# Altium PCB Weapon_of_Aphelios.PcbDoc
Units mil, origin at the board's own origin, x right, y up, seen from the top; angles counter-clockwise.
Board outline 1771.65 x 1968.5 mil, 2 copper layers (Top Layer, Bottom Layer); 49 components, 29 nets, 186 pads, 53 vias.
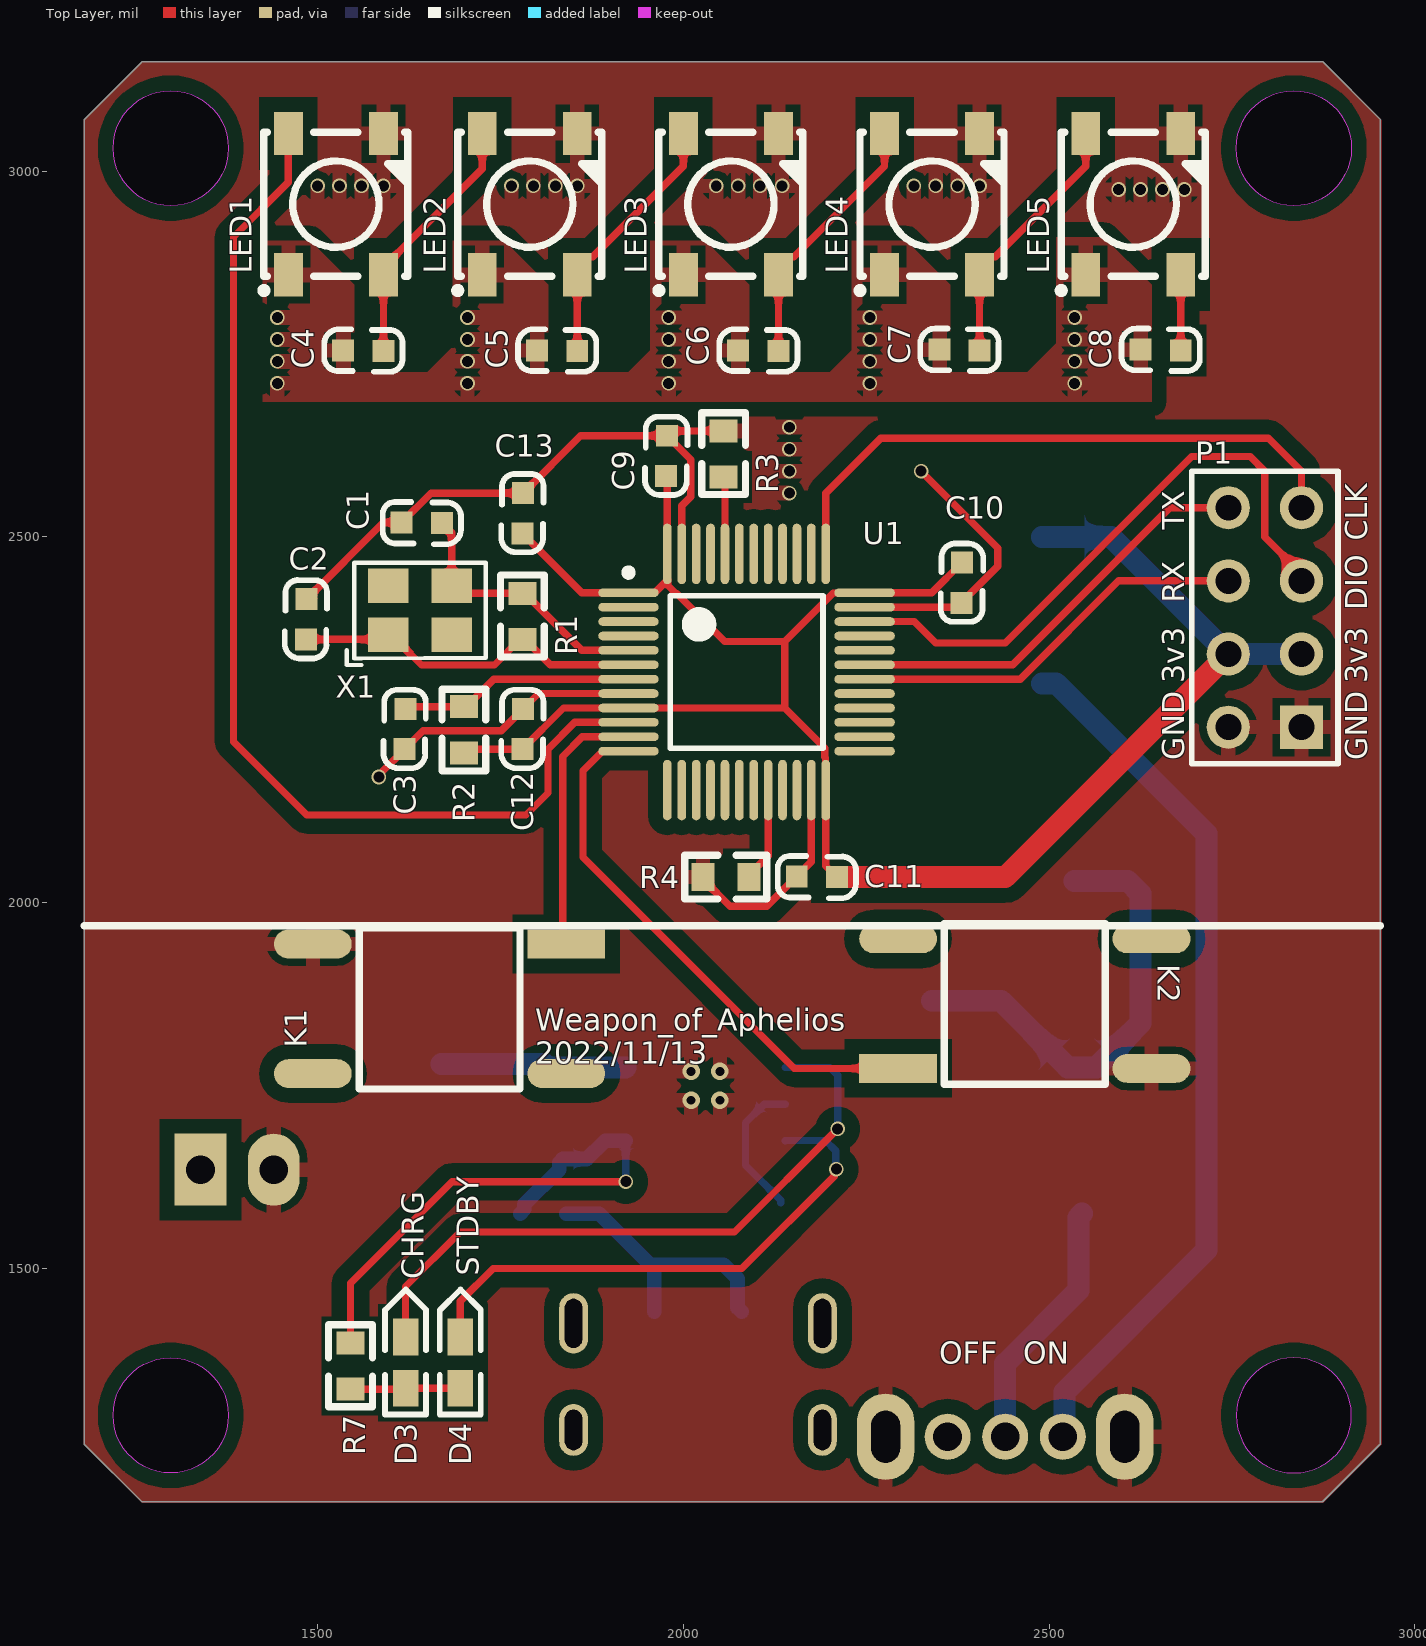
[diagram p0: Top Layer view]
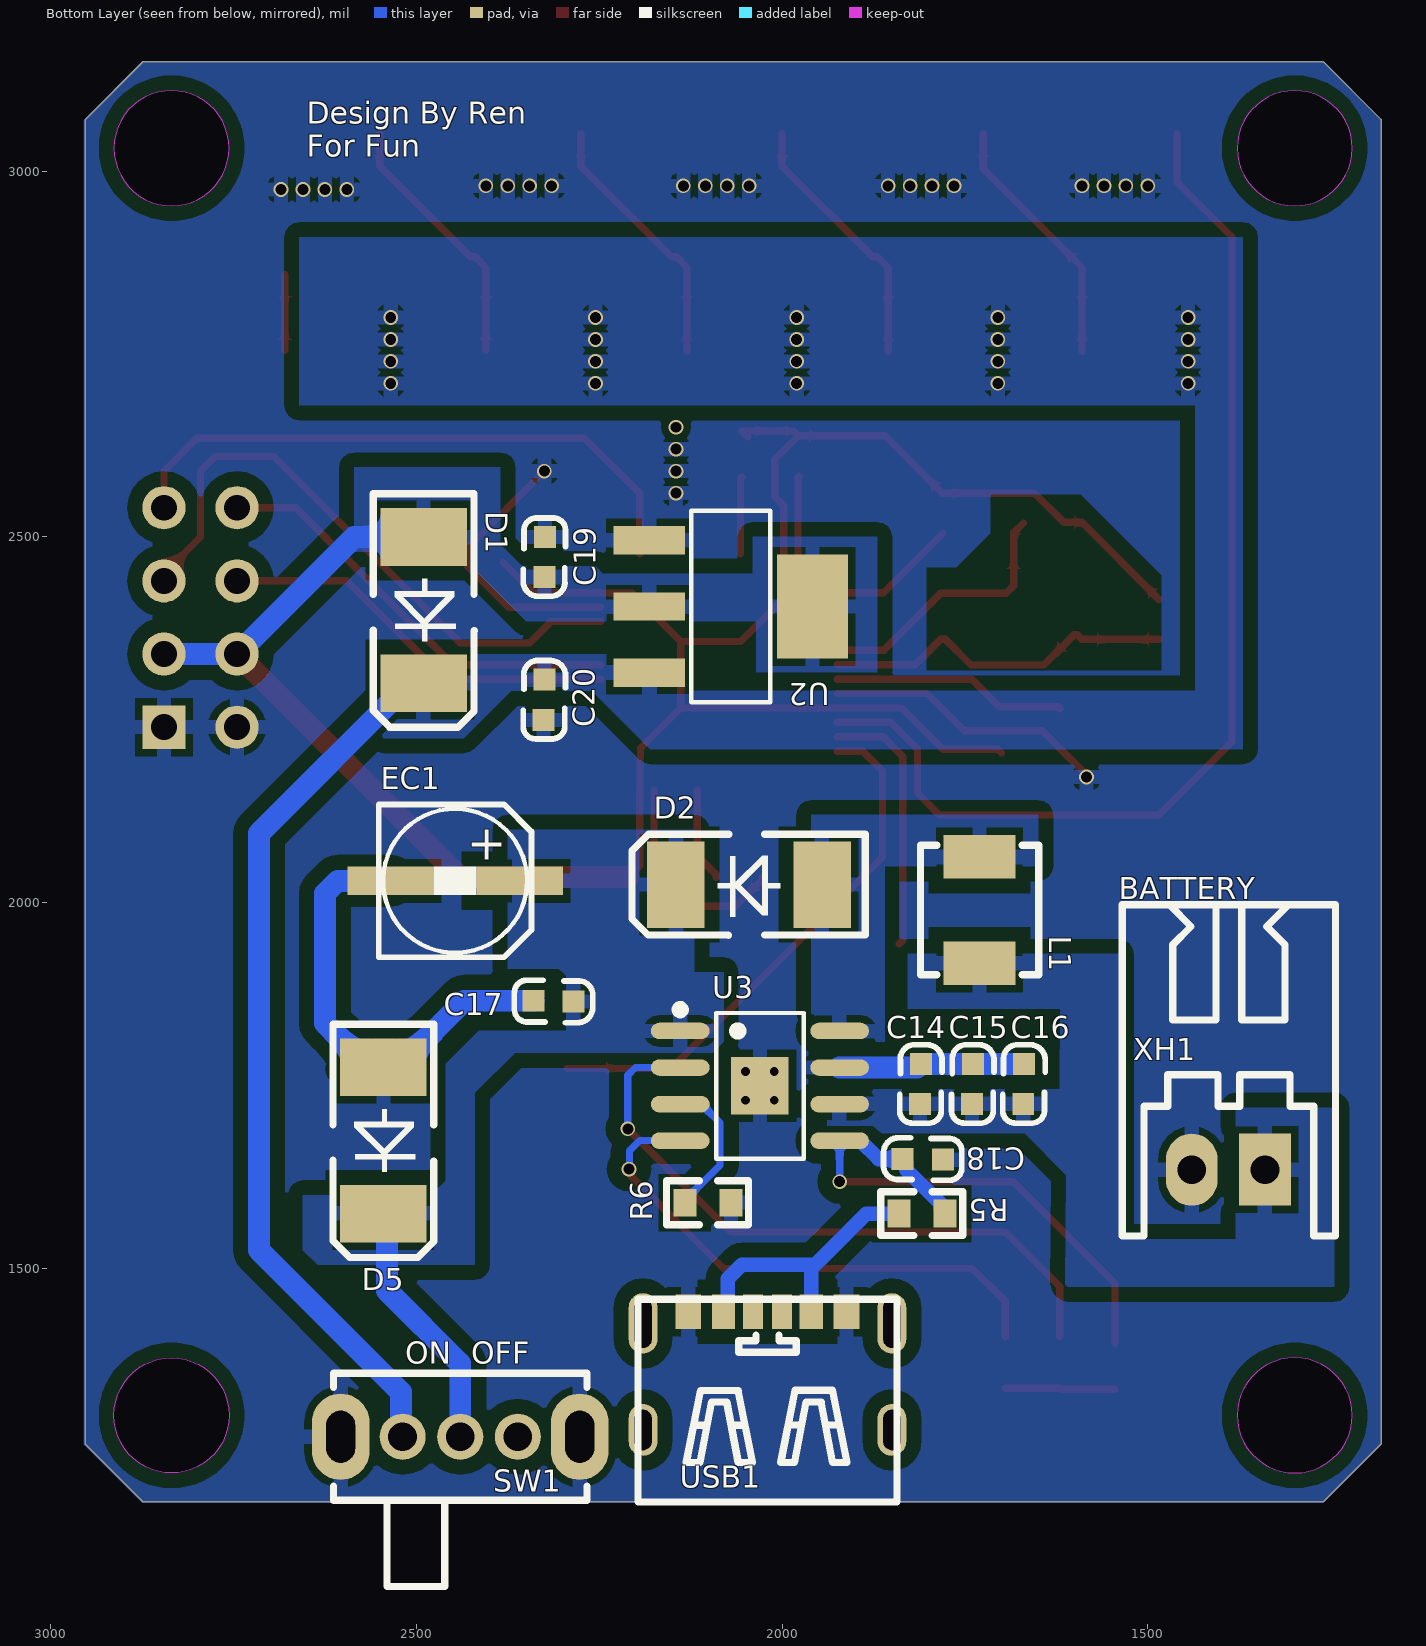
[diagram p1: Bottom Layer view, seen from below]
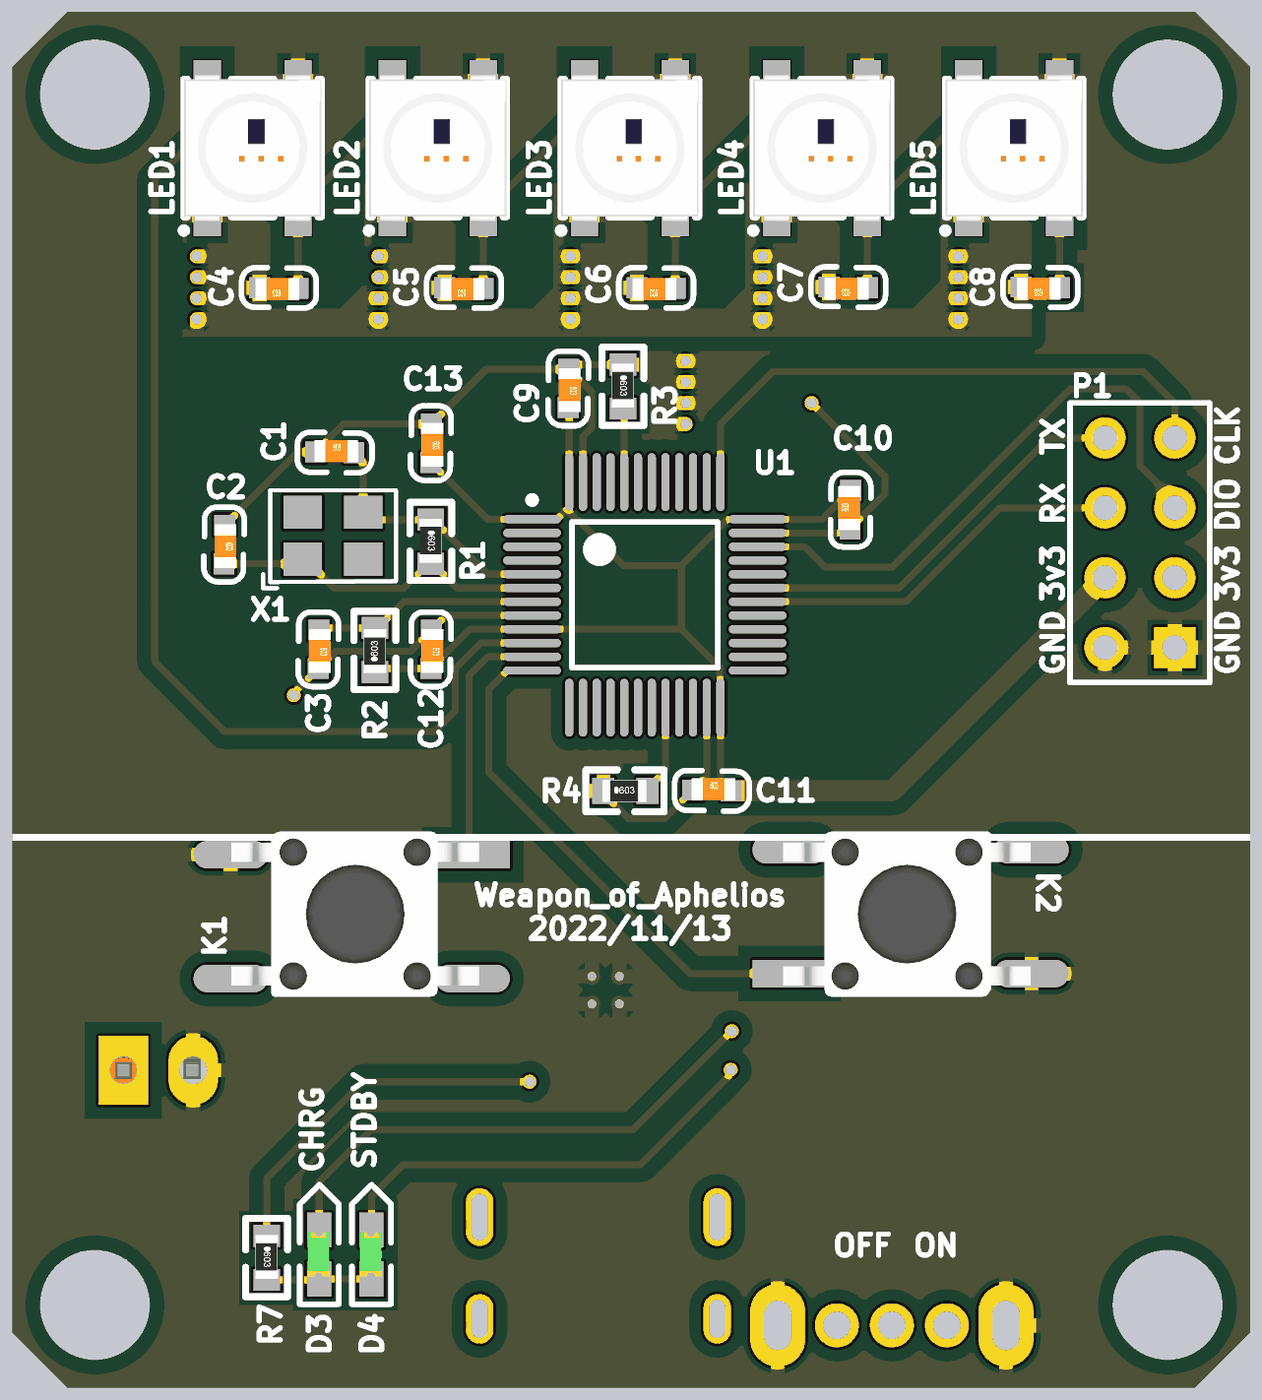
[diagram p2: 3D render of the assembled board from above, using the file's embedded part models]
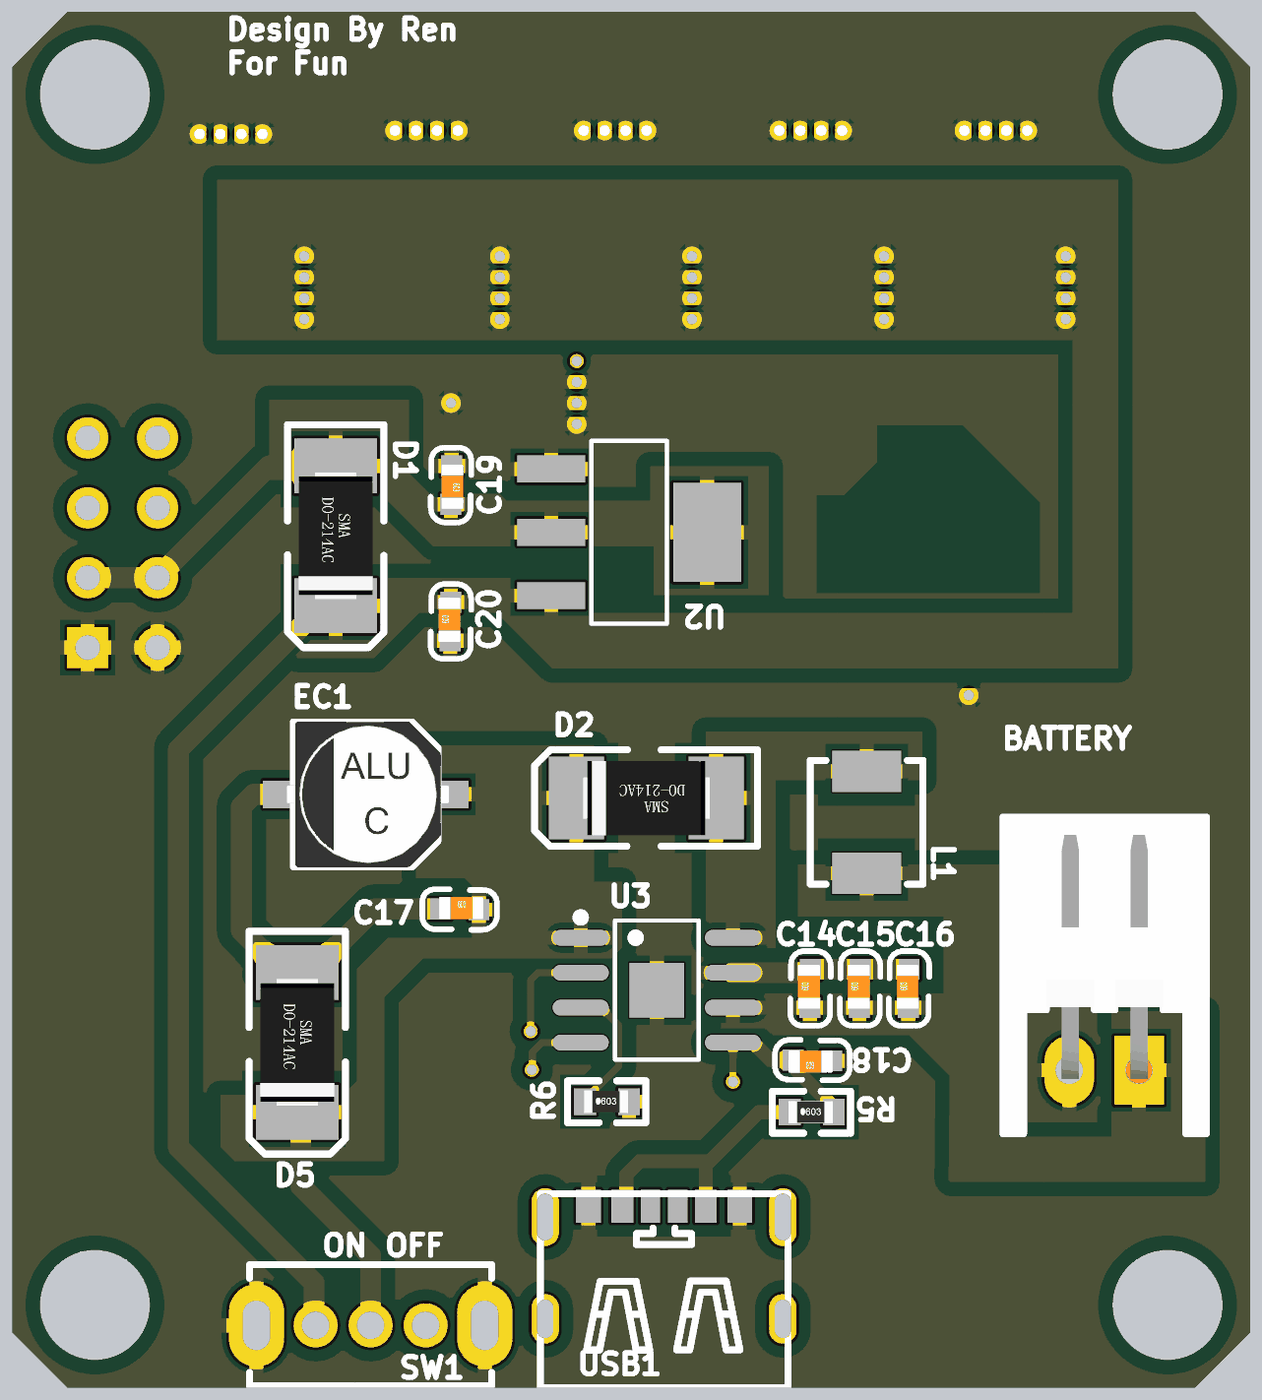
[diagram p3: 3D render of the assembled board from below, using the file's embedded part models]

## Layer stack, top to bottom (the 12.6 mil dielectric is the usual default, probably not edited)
Top Solder: solder mask 0.4, Solder Resist, Dk 3.5
Top Layer: signal copper 1.4
Dielectric 1: dielectric 12.6, FR-4, Dk 4.8
Bottom Layer: signal copper 1.4
Bottom Solder: solder mask 0.4, Solder Resist, Dk 3.5

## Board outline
1259.84,1181.1 1181.1,1259.84 1181.1,3070.87 1259.84,3149.61 2874.02,3149.61 2952.76,3070.87 2952.76,1259.84 2874.02,1181.1
cut-out: 1299.21,1220.47 cw(c1299.21,1299.21) 1220.47,1299.21 cw(c1299.21,1299.21) 1299.21,1377.95 cw(c1299.21,1299.21) 1377.95,1299.21 cw(c1299.21,1299.21)
cut-out: 2755.91,1299.21 ccw(c2834.65,1299.21) 2834.65,1220.47 ccw(c2834.65,1299.21) 2913.39,1299.21 ccw(c2834.65,1299.21) 2834.65,1377.95 ccw(c2834.65,1299.21)
cut-out: 2834.65,2952.76 cw(c2834.65,3031.5) 2755.91,3031.5 cw(c2834.65,3031.5) 2834.65,3110.24 cw(c2834.65,3031.5) 2913.39,3031.5 cw(c2834.65,3031.5)
cut-out: 1299.21,2952.76 cw(c1299.21,3031.5) 1220.47,3031.5 cw(c1299.21,3031.5) 1299.21,3110.24 cw(c1299.21,3031.5) 1377.95,3031.5 cw(c1299.21,3031.5)

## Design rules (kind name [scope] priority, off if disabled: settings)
Clearance MCU [InComponent('U1') vs InComponent('U1')] p1: gap=8 ignorepadtopadclearanceinfootprint=TRUE except(0: Arc-Hole Track-Hole SMDPad-Hole THPad-Hole Via-Hole Fill-Hole Poly-Hole Region-Hole Text-Hole)
Clearance [All] p2: gap=8 ignorepadtopadclearanceinfootprint=TRUE except(0: Arc-Hole Track-Hole SMDPad-Hole THPad-Hole Via-Hole Fill-Hole Poly-Hole Region-Hole Text-Hole)
PlaneConnect [All] p1: planeconnectstyle=Relief reliefexpansion=20 reliefentries=4 reliefconductorwidth=20 reliefairgap=10
PolygonConnect [All] p1: connectstyle=Relief reliefconductorwidth=20 reliefentries=4 polygonreliefangle="90 Angle" airgapwidth=10
RoutingVias [All] p1: holewidth=15 width=20 viastyle="Through Hole" minholewidth=15 minwidth=20 maxholewidth=30 maxwidth=40
SolderMaskExpansion [All] p1: expansion=4 istentingtop=FALSE
Width [All] p1: maxlimit=30 minlimit=10 preferedwidth=20
29 further rules are at their usual default settings.

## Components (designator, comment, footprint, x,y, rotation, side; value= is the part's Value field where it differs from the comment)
C1 "22pF" 0603C 1614.79,2520.35 r0 top
C2 "22pF" 0603C 1485.35,2415.21 r270 top
C3 "100nF" 0603C 1620.35,2265.21 r270 top
C4 "100nF" 0603C 1590.21,2753.65 r180 top
C5 "100nF" 0603C 1855.21,2753.65 r180 top
C6 "100nF" 0603C 2130.21,2753.65 r180 top
C7 "100nF" 0603C 2405.21,2754.65 r180 top
C8 "100nF" 0603C 2680.21,2754.65 r180 top
C9 "100nF" 0603C 1977.93,2638.64 r270 top
C10 "100nF" 0603C 2379.65,2409.79 r90 top
C11 "100nF" 0603C 2154.79,2036.35 r0 top
C12 "100nF" 0603C 1781.35,2265.21 r270 top
C13 "100nF" 0603C 1781.35,2560.21 r270 top
C14 "0.1uF" 0603C 1811.65,1724.49 r90 bottom
C15 "22uF" 0603C 1740.65,1724.49 r90 bottom
C16 "22uF" 0603C 1670.65,1724.49 r90 bottom
C17 "100nF" 0603C 2340.21,1866.35 r180 bottom
C18 "10uF" 0603C 1780.09,1648.35 r0 bottom
C19 "10uF" 0603C 2323.65,2500.21 r270 bottom
C20 "10uF" 0603C 2326.35,2249.79 r90 bottom
D1 "SS34-MS" SMA/DO-214AC 2490,2495 r270 bottom
D2 "SS34-MS" SMA/DO-214AC 1950.3,2024.7 r0 bottom
D3 "CHRG" LED-0603B 1620.56,1336.3 r90 top
D4 "STDBY" LED-0603B 1695.3,1336.3 r90 top
D5 "SMAJ6.0A" SMA/DO-214AC 2545,1770 r270 bottom
EC1 "47uF" SMD-EC5.0X5.3X5.4 2358.75,2030 r0 bottom
K1 "KEY" SMD-6X6X6 1836.77,1945.43 r270 top
K2 "KEY" SMD-6X6X6 2296.77,1771.65 r90 top
L1 "10uH" IND-SMD_L4.5-W4.1_TMPA0402SP 1730,1990 r270 bottom
LED1 "WS2812B-B" LED-SMD_4P-L5.0-W5.0-TL_WS2812B-B 1525,2955 r90 top
LED2 "WS2812B-B" LED-SMD_4P-L5.0-W5.0-TL_WS2812B-B 1790,2955 r90 top
LED3 "WS2812B-B" LED-SMD_4P-L5.0-W5.0-TL_WS2812B-B 2065,2955 r90 top
LED4 "WS2812B-B" LED-SMD_4P-L5.0-W5.0-TL_WS2812B-B 2340,2955 r90 top
LED5 "WS2812B-B" LED-SMD_4P-L5.0-W5.0-TL_WS2812B-B 2615,2955 r90 top
P1 "Header 4X2" HDR2X4 2845,2240 r90 top
R1 "1M" 0603R 1780,2422.99 r270 top
R2 "10K" 0603R 1700,2205 r90 top
R3 "10K" 0603R 2055,2645 r270 top
R4 "10K" 0603R 2027.01,2035 r0 top
R5 "0.3" 0603R 1840,1575 r180 bottom
R6 "3k" 0603R 2132.99,1590 r180 bottom
R7 "1K" 0603R 1545,1397.99 r270 top
SW1 "SK12D07VG3_C431547" SW-TH_SK12D07VG3 2440,1270 r180 bottom
U1 "STM32F103C" LQFP-48_M 2086.42,2315.47 r0 top
U2 "AMS1117-3.3_C369933" SOT-223-4_L6.5-W3.5-P2.30-LS7.0-BR 2070,2405 r0 bottom
U3 "TP5400" SOIC-8_L5.0-W4.0-P1.27-LS6.0-BL-EP2.0 2030.3,1749.7 r270 bottom
USB1 "TYPE-C-31-M-16" TYPE-C-31-M-16 2020,1360 r180 bottom
X1 "8MHz" OSC-SMD_4P-L3.2-W2.5-BL 1640,2400 r0 top
XH1 "XH2" XH2/2.54mm/90 1340,1635 r0 bottom

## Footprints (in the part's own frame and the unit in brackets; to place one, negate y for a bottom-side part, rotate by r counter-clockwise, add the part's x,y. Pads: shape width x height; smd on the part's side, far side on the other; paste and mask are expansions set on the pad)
0603C [mil]
  rect 30x30 smd: 1(0.21,-0.35) 2(55.21,-1.35)
  silkscreen extent -26,-30 81,28, body extent -1,-15 62,17, height 12
0603R [mm]
  rect 0.8x0.965 smd: 1(0,0) 2(1.6,0)
  silkscreen extent -0.64,-0.76 2.21,0.76, body extent -0.04,-0.41 1.56,0.41, height 0.45
HDR2X4 [mm] "Connector; Header; 4x2 Position"
  rect 1.5x1.5 hole 0.9: 1(0,0)
  round 1.5 hole 0.9: 2(0,2.54) 3(2.54,0) 4(2.54,2.54) 5(5.08,0) 6(5.08,2.54) 7(7.62,0) 8(7.62,2.54)
  silkscreen extent -1.27,-1.27 8.89,3.81
IND-SMD_L4.5-W4.1_TMPA0402SP [mm]
  rect 1.5x2.5 smd mask+0.051: 1(-1.85,0) 2(1.85,0)
  silkscreen extent -2.25,-2.05 2.25,2.05
LED-0603B [mil]
  rect 50x35 smd: A(0,0.26) K(70,0.26)
  silkscreen extent -36,-28 135,28, body extent 4,-15 66,17, height 24
LED-SMD_4P-L5.0-W5.0-TL_WS2812B-B [mm]
  rect 1.5x1 smd mask+0.051: 1(-2.45,1.65) 2(-2.45,-1.65) 3(2.45,-1.65) 4(2.45,1.65)
  silkscreen extent -3.1,-2.5 2.5,2.6, body extent -2.7,-2.5 2.7,2.5, height 1.57
LQFP-48_M [mm] "Thin QFP, 48-Leads, Body 7x7mm, Pitch 0.5mm, IPC Low Density"
  oval 2.1x0.3 smd: 1(-4.1,2.75) 2(-4.1,2.25) 3(-4.1,1.75) 4(-4.1,1.25) 5(-4.1,0.75) 6(-4.1,0.25) 7(-4.1,-0.25) 8(-4.1,-0.75) 9(-4.1,-1.25) 10(-4.1,-1.75) 11(-4.1,-2.25) 12(-4.1,-2.75) 25(4.1,-2.75) 26(4.1,-2.25) 27(4.1,-1.75) 28(4.1,-1.25) 29(4.1,-0.75) 30(4.1,-0.25) 31(4.1,0.25) 32(4.1,0.75) 33(4.1,1.25) 34(4.1,1.75) 35(4.1,2.25) 36(4.1,2.75)
  oval 0.3x2.1 smd: 13(-2.75,-4.1) 14(-2.25,-4.1) 15(-1.75,-4.1) 16(-1.25,-4.1) 17(-0.75,-4.1) 18(-0.25,-4.1) 19(0.25,-4.1) 20(0.75,-4.1) 21(1.25,-4.1) 22(1.75,-4.1) 23(2.25,-4.1) 24(2.75,-4.1) 37(2.75,4.1) 38(2.25,4.1) 39(1.75,4.1) 40(1.25,4.1) 41(0.75,4.1) 42(0.25,4.1) 43(-0.25,4.1) 44(-0.75,4.1) 45(-1.25,4.1) 46(-1.75,4.1) 47(-2.25,4.1) 48(-2.75,4.1)
  silkscreen extent -4.22,-2.65 2.65,3.57, body extent -3.5,-3.5 3.5,3.5, height 1.6
OSC-SMD_4P-L3.2-W2.5-BL [mm]
  rect 1.4x1.2 smd: 1(-1.1,-0.851) 2(1.1,-0.851) 3(1.1,0.851) 4(-1.1,0.851)
  silkscreen extent -2.54,-1.91 2.29,1.65
SMA/DO-214AC [mm] "塑封二极管"
  rect 2x3 smd: A(-0.127,0) K(4.953,0)
  silkscreen extent -1.63,-1.75 6.48,1.75, body extent 0.11,-1.35 4.71,1.35, height 2.4
SMD-6X6X6 [mm]
  rect 1x2.7 smd: 1(0.047,0.082)
  oval 1x2.7 smd: 2(4.547,0.082) 3(0.047,-8.718) 4(4.547,-8.718)
  silkscreen extent -0.51,-7.11 5.08,-1.52, body extent -0.79,-8.69 5.21,0.31, height 5.95
SMD-EC5.0X5.3X5.4 [mm]
  rect 3x1 smd: 1(0,0) 2(4.477,0)
  silkscreen extent -0.41,-2.65 4.89,2.66, body extent -0.79,-2.65 5.11,2.65, height 5.41
SOIC-8_L5.0-W4.0-P1.27-LS6.0-BL-EP2.0 [mil]
  oval 22.6x80.2 smd mask+2: 1(-75,-109) 2(-25,-109) 3(25,-109) 4(75,-109) 5(75,109) 6(25,109) 7(-25,109) 8(-75,109)
  rect 78.7x78.7 smd mask+2: 9(0,0)
  silkscreen extent -110,-115 100,60
SOT-223-4_L6.5-W3.5-P2.30-LS7.0-BR [mm]
  rect 2.47x0.98 smd: 1(2.835,-2.3) 2(2.835,0) 3(2.835,2.3)
  rect 2.47x3.6 smd: 4(-2.835,0)
  silkscreen extent -1.37,-3.33 1.37,3.33
SW-TH_SK12D07VG3 [mm]
  round 1.6 hole 1: 1(-2,0) 2(0,0) 3(2,0)
  oval 2x3 hole 1 slot 1.8 at 90 deg: 4(4.15,0) 5(-4.15,0)
  silkscreen extent -4.4,-5.2 4.4,2.2
TYPE-C-31-M-16 [mm]
  oval 1x2.1 hole 0.6 slot 1.7 at 90 deg: 1(-4.32,1.65) 2(4.32,1.65)
  oval 1x1.8 hole 0.6 slot 1.4 at 90 deg: 3(-4.32,-2.05) 4(4.32,-2.05)
  rect 0.7x1.2 smd: A5(-0.5,2.05) B5(0.5,2.05)
  rect 0.8x1.2 smd: A9(1.52,2.05) B9(-1.52,2.05)
  rect 0.9x1.2 smd: A12(2.75,2.05) B12(-2.75,2.05)
  silkscreen extent -4.5,-4.55 4.5,2.49
XH2/2.54mm/90 [mm]
  rect 1.8x2.5 hole 1: 1(0,0)
  oval 1.8x2.5 hole 1: 2(2.54,0)
  silkscreen extent -2.45,-9.2 4.95,2.3, body extent -2.45,-9.2 4.95,2.3, height 6.1

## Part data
C1 C2: library part CAP
C3 C4 C5 C6 C7 C8 C9 C10 C11 C12 C13 C14 C15 C16 C17 C18 C19 C20: library part CAP, "无极性电容"
D1 D2: library part "DIODE SCHOTTKY", "肖特基二极管"
D3 D4: library part LED
D5: library part "DIODE ZENER", "瞬态二极管 SMAJ6.0A DO-214AC 6.0V"
EC1: library part SMD_ECAP, "贴片电解电容"
L1: library part TMPC0402HP-100MG-Z02, DC Resistance (DCR)=215mΩ, JLCPCB Part Class="Extended Part", LCSC Part Name="10uH ±20% 1.4A 215mΩ", Manufacturer=台庆, Rated Current=1.4A, Tolerance=±20%
LED1 LED2 LED3 LED4 LED5: Emitted Color=RGB三色, JLCPCB Part Class="Extended Part", LCSC Part Name="RGB三色 （注意防潮，请查阅规格书中对应具体内容）", Manufacturer=worldsemi
P1: "Header, 4-Pin, Dual row"
R1 R2 R3 R4 R5 R6 R7: library part RES
SW1: BOM_JLCPCB Part Class="Extended Part", BOM_Manufacturer="SHOU HAN", BOM_Manufacturer Part=SK12D07VG3
U1: "STM32单片机48引脚"
U2: BOM_Manufacturer=KEXIN, BOM_Manufacturer Part=AMS1117-3.3
U3: Battery Pack Voltage=-, JLCPCB Part Class="Extended Part", Manufacturer=TOPPOWER(南京拓微)
X1: library part "8MHz 10pF ±10ppm", BOM_Manufacturer="Zhejiang Abel Elec", BOM_Manufacturer Part=TAXM8M4RDBCCT2T

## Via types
v1: diameter 20, hole 15, Top Layer to Bottom Layer, 49 vias
v2: diameter 24, hole 12, Top Layer to Bottom Layer, 4 vias

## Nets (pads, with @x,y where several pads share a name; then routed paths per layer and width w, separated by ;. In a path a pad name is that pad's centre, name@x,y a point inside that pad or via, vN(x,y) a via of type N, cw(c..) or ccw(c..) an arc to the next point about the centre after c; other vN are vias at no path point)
3v3: C9.2 C10.2 C11.2 C12.2 C13.2 C19.2 D1.A P1.3 P1.4 R2.1 U1.1 U1.9 U1.24 U1.36 U1.48 U2.2 U2.4 | length 2766.3
  Top Layer w10: R2.1 1705,2210 C12.2 1836.26,2266.26 U1.9 2138.74,2266.26 ; C13.2 1861.26,2423.74 U1.1 1960.78,2423.74 1978.5,2441.46 1978.5,2434.06 ; C9.2 1978.15,2581.85 U1.48 U1.48@1978.15,2441.46 ; 1978.93,2433.63 1990,2422.55 1991.23,2422.55 2056.65,2357.13 2138.74,2357.13 ; C11.2 2194.68,2050.32 U1.24 2194.34,2154.4 2194.34,2198.53 2193.5,2199.37 2193.5,2211.5 2138.74,2266.26 ; C10.2 2339.74,2423.74 U1.36 2247.49,2423.39 2205,2423.39 2138.74,2357.13 ; 2138.74,2266.26 2138.74,2357.13
  Top Layer w30: C11.2 2440,2035 P1.4
  Bottom Layer w30: D1.A 2585,2500 P1.4 P1.3
5V: C4.2 C5.2 C6.2 C7.2 C8.2 C20.2 D1.K LED1.1 LED2.1 LED3.1 LED4.1 LED5.1 SW1.1 U2.3 | length 1216
  Bottom Layer w30: D1.K 2509.68,2300 2715,2094.68 2715,1525 2520.96,1330.96 2520.96,1272.22 SW1.1
  other v1: 1445,2710 1705,2710 1980,2710 2255,2710 2535,2710 1445,2740 1705,2740 1980,2740 2255,2740 2535,2740 1445,2770 1705,2770 1980,2770 2255,2770 2535,2770 1445,2800 1705,2800 1980,2800 2255,2800 2535,2800
BAT: C14.1 C15.1 C16.1 L1.2 U3.6 XH1.1
DIN: LED1.4 U1.10 | length 1531.5
  Top Layer w10: LED1.4 1460.04,2985.04 1385,2910 1385,2220 1485,2120 1785,2120 1815,2150 1815,2210 1851.57,2246.57 U1.10
GND: C1.1 C2.1 C3.2 C9.1 C10.1 C11.1 C12.1 C13.1 C14.2 C15.2 C16.2 C17.1 C18.1 C19.1 C20.1 D5.A EC1.2 K1.3 K2.3 LED1.3 LED2.3 LED3.3 LED4.3 LED5.3 P1.1 P1.2 R3.1 R4.1 R6.2 SW1.4 SW1.5 U1.8 U1.23 U1.35 U1.47 U2.1 U3.7 U3.9 USB1.A12 USB1.B12 XH1.2 | length 2791.5
  Top Layer w10: C2.1 1590,2520 C1.1 1655,2560 C13.1 1859.43,2638.43 C9.1 ; v1(1583.83,2171.83) 1585.74,2173.74 1585.74,2176.74 C3.2 1644,2235 1751,2235 C12.1 1801.94,2285.94 U1.8 ; U1.47 1997.83,2542.83 2010,2555 2010,2606 C9.1 ; R4.1 2027.01,2031.75 2063.76,1995 2114,1995 C11.1 2175,2056 U1.23 ; R3.1@2047.01,2637.01 R3.1 1984.15,2645 C9.1 ; U1.35 2374.06,2404.06 C10.1 2430,2460 2430,2485 v1(2325,2590)
  Bottom Layer w30: C16.2 C15.2 C14.2 1815.3,1774.7 U3.7 ; C17.1 2434.32,1866 2525.32,1775 D5.A 2564.68,1775 2625,1835.32 2625,2012.43 2607.43,2030 EC1.2
  other v1: 2145,2560 2145,2590 2145,2620 2145,2650 2595,2975 2625,2975 2655,2975 2685,2975 1500,2980 1530,2980 1560,2980 1590,2980 1765,2980 1795,2980 1825,2980 1855,2980 2045,2980 2075,2980 2105,2980 2135,2980 2315,2980 2345,2980 2375,2980 2405,2980
  other v2: 2010.6,1730 2050,1730 2010.6,1769.4 2050,1769.4
KEY1: K1.1 U1.11 | length 359.6
  Top Layer w10: K1.1 1835,1948.6 1835,2200 1861.89,2226.89 U1.11
KEY2: K2.1 U1.12 | length 741.8
  Top Layer w10: U1.12 1889.57,2207.2 1862.82,2180.46 1862.82,2062.18 2151.51,1773.49 K2.1
NetC1_2: C1.2 R1.1 U1.5 X1.3 | length 369.4
  Top Layer w10: C1.2 1683.3,2505.7 X1.3 1693.82,2422.99 R1.1 1783.25,2422.99 1861.24,2345 U1.5
NetC2_2: C2.2 R1.2 U1.6 X1.1 | length 489.7
  Top Layer w10: C2.2 1590.19,2360 X1.1 1600.63,2366.5 1642.13,2325 1741.75,2325 1776.75,2360 R1.2 1783.25,2360 1817.93,2325.32 U1.6
NetC3_1: C3.1 R2.2 U1.7 | length 321.8
  Top Layer w10: C3.1 1622.99,2267.99 R2.2 1703.25,2267.99 1740.89,2305.63 U1.7
NetC4_1: C4.1 LED1.2 LED2.4 | length 353.4
  Top Layer w10: C4.1 LED1.2 LED1.2 1589.96,2868.39 1725.04,3003.47 LED2.4
NetC5_1: C5.1 LED2.2 LED3.4 | length 361.4
  Top Layer w10: C5.1 LED2.2 LED2.2 1854.96,2868.39 1869.64,2883.07 1876.18,2883.07 2000.04,3006.93 LED3.4
NetC6_1: C6.1 LED3.2 LED4.4 | length 361.4
  Top Layer w10: C6.1 LED3.2 LED3.2 2129.96,2868.39 2144.64,2883.07 2151.18,2883.07 2275.04,3006.93 LED4.4
NetC7_1: C7.1 LED4.2 LED5.4 | length 360.4
  Top Layer w10: C7.1 C7.1 LED4.2 2404.96,2868.39 2419.64,2883.07 2426.18,2883.07 2550.04,3006.93 LED5.4
NetC8_1: C8.1 LED5.2 | length 103.6
  Top Layer w10: LED5.2 C8.1 C8.1
NetC18_2: C18.2 R5.2 R7.1 U3.5 | length 767
  Top Layer w10: R7.1 1545,1480 1683.7,1618.7 v1(1921.3,1618.7)
  Bottom Layer w10: v1(1921.3,1618.7) U3.5
  Bottom Layer w20: R5.2 1782.76,1580.75 1782.76,1587.76 1830.3,1635.3 1830.3,1644.7 C18.2 1868.2,1649.7 1892,1673.5 1893.2,1674.7 U3.5
NetD2_A: D2.A L1.1 U3.8
NetD3_A: D3.A D4.A R7.2 | length 150.6
  Top Layer w10: R7.2 1619,1335 D3.A D4.A
NetD3_K: D3.K U3.2 | length 898.1
  Top Layer w10: D3.K 1620.3,1475.3 1695,1550 2070,1550 v1(2210.89,1690.89)
  Bottom Layer w10: U3.2 2200.3,1774.7 2210.89,1764.11 v1(2210.89,1690.89)
NetD4_K: D4.K U3.4 | length 742
  Top Layer w10: D4.K 1695.04,1455.04 1740,1500 2080,1500 2206.29,1626.29 2206.29,1630.08 2209.25,1633.04 v1(2209.25,1635.75)
  Bottom Layer w10: U3.4 2139.45,1674.85 2194.4,1674.85 2208.5,1660.75 2208.5,1636.5 v1(2209.25,1635.75)
NetR3_2: R3.2 U1.44 | length 105.9
  Top Layer w10: R3.2 2056.89,2580.12 U1.44
NetR4_2: R4.2 U1.20 | length 129.8
  Top Layer w10: R4.2 2090,2038.25 2115.94,2064.19 U1.20
NetR6_1: R6.1 U3.3 | length 193.9
  Bottom Layer w10: R6.1 2132.99,1593.25 2085,1641.24 2085,1699.2 2110.5,1724.7 U3.3
SWCLK: P1.7 U1.37 | length 832.9
  Top Layer w10: U1.37 2194.68,2559.68 2270,2635 2800,2635 2845,2590 P1.7
SWDIO: P1.5 U1.34 | length 844
  Top Layer w10: U1.34 2315.63,2384.37 2345,2355 2440,2355 2695,2610 2775,2610 2795,2590 2795,2500 2845,2450 P1.5
USART1_RX: P1.8 U1.31 | length 586.1
  Top Layer w10: U1.31 2450.32,2325.32 2665,2540 P1.8
USART1_TX: P1.6 U1.30 | length 552.8
  Top Layer w10: U1.30 2460.63,2305.63 2595,2440 P1.6
VCC: R5.1 USB1.A9 USB1.B9 | length 385
  Bottom Layer w20: R5.1 1885,1575 1955,1505 ; USB1.A9 1960.15,1499.85 1955,1505 ; USB1.B9 2074.1,1446.46 2074.1,1485.9 2055,1505 1955,1505
VOUT: C17.2 D2.K D5.K EC1.1 SW1.2 U3.1 | length 340
  Bottom Layer w30: SW1.2@2440,1278.54 2440,1370 2540,1470 2540,1570 D5.K
pads on no net: K1.2 K1.4 K2.2 K2.4 SW1.3 U1.2 U1.3 U1.4 U1.13 U1.14 U1.15 U1.16 U1.17 U1.18 U1.19 U1.21 U1.22 U1.25 U1.26 U1.27 U1.28 U1.29 U1.32 U1.33 U1.38 U1.39 U1.40 U1.41 U1.42 U1.43 U1.45 U1.46 USB1.1 USB1.2 USB1.3 USB1.4 USB1.A5 USB1.B5 X1.2 X1.4

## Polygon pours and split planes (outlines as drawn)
GND on Top Layer "GND_L01_P011" (solid, remove dead copper, pour order 11): 1260,3150 2875,3150 2955,3070 2955,1260 2875,1180 1260,1180 1180,1260 1180,3070
5V on Top Layer "5V_L01_P001" (solid, remove dead copper, pour order 1): 1425,2685 2640,2685 2640,2845 2575,2910 2510,2910 2510,2765 2470,2725 2365,2725 2365,2845 2305,2905 2230,2905 2230,2755 2200,2725 2090,2725 2090,2845 2030,2905 1955,2905 1955,2755 1925,2725 1815,2725 1815,2845 1755,2905 1685,2905 1685,2760 1650,2725 1550,2725 1550,2845 1490,2905 1425,2905
GND on Bottom Layer "GND_L02_P012" (solid, remove dead copper, pour order 12): 1260,3150 2875,3150 2955,3070 2955,1260 2875,1180 1260,1180 1180,1260 1180,3070
BAT on Bottom Layer "BAT_L02_P002" (solid, remove dead copper, pour order 2): 1380,1540 1380,1720 1245,1720 1245,1475 1612.72,1475 1611.24,1627.8 1668.44,1685 1863.44,1685 1875.94,1695 1938.44,1695 1938.44,1745 1620.16,1745 1619.84,1855 1828.44,1855 1828.44,1930 1540,1930 1540,1540
VOUT on Bottom Layer "VOUT_L02_P003" (solid, remove dead copper, pour order 3): 2375,2100 2120,2100 2120,1905 2080,1905 2080,1810 2095,1795 2365,1795 2420,1740 2420,1505 2635,1505 2655,1525 2655,1600 2480,1600 2460,1620 2460,1780 2415,1825 2295,1825 2295,1900 2305,1910 2375,1910
3v3 on Bottom Layer "3V3_L02_P004" (solid, remove dead copper, pour order 4): 2585,2595 2385,2595 2385,2490 2355,2460 2255,2460 2245,2450 2040,2450 2040,2500 1870,2500 1870,2315 2035,2315 2035,2385 2350,2385 2445,2480 2585,2480
5V on Bottom Layer "5V_L02_P005" (solid, remove dead copper, pour order 5): 2585,2225 2435,2225 2370,2290 2260,2290 2180,2210 1370,2210 1370,2910 2660,2910 2660,2680 1435.44,2680 1435.44,2290 2130,2290 2130,2340 2585,2340
NetD2_A on Bottom Layer "NETD2_A_L02_P006" (solid, remove dead copper, pour order 6): 1650,2050 1860,2050 1860,1810 1960,1810 1960,2120 1650,2120

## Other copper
Top Layer:
  pour cut-out: 1805,2460 1765,2460 1718,2507 1718,2560 1595,2560 1485,2450 1485,2320 1805,2320
Bottom Layer:
  pour cut-out: 1802,2458 1762,2458 1715,2505 1715,2558 1592,2558 1482,2448 1482,2318 1802,2318

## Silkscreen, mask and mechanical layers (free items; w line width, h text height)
Top Overlay:
  lines w10: 1181.1,1968.5 2952.76,1968.5
  text "TX" at 2685,2510 h30 r90
  text "CLK" at 2935,2495 h30 r90
  text "RX" at 2685,2410 h30 r90
  text "DIO" at 2935,2400 h30 r90
  text "3v3" at 2685,2300 h30 r90
  text "3v3" at 2935,2300 h30 r90
  text "GND" at 2685,2195 h30 r90
  text "GND" at 2935,2195 h30 r90
  text "Weapon_of_Aphelios / 2022/11/13" at 1797.58,1780 h30
  text "STDBY" at 1720,1490 h30 r90
  text "CHRG" at 1645,1485 h30 r90
  text "OFF" at 2350,1370 h30
  text "ON" at 2465,1370 h30
Bottom Overlay:
  text "Design By Ren / For Fun" at 2650,3020 h30
  text "BATTERY" at 1540,2005 h30
  text "OFF" at 2425,1370 h30
  text "ON" at 2515,1370 h30
Mechanical 1:
  circle w10: c2834.65,3031.5 r78.74
  circle w10: c1299.21,3031.5 r78.74
  circle w10: c1299.21,1299.21 r78.74
  circle w10: c2834.65,1299.21 r78.74
  lines w10: 1259.84,3149.61 1181.1,3070.87 1181.1,1259.84 1259.84,1181.1 2874.02,1181.1 2952.76,1259.84 ; 1259.84,3149.61 1259.84,3149.61 ; 1259.84,3149.61 2874.02,3149.61 2952.76,3070.87 2952.76,1259.84 ; 2952.76,1259.84 2952.76,1259.84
